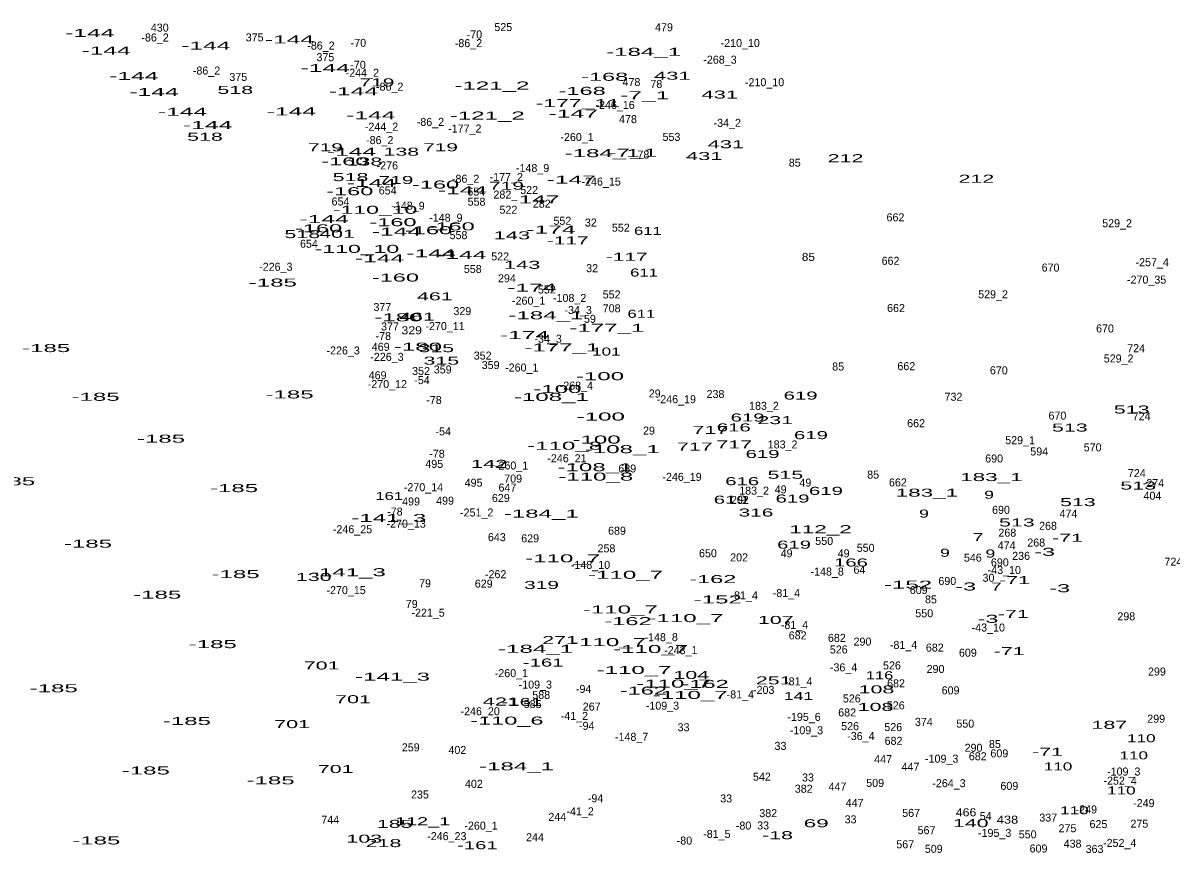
# Model space of a CAD drawing. Extents: x -658595 to -655205, y -1004347 to -1000147.
# Drawn here: x -656989 to -656415, y -1001888 to -1001473 of the extents above; entities that cross this region are included whole.
import ezdxf
from ezdxf.enums import TextEntityAlignment as Align

# ---------------------------------------------------------------- set-up
doc = ezdxf.new("R2010")
doc.units = 0
doc.header["$LTSCALE"] = 1.6
doc.layers.add('24', color=7, linetype='Continuous')

msp = doc.modelspace()

# ---------------------------------------------------------------- texts
at = {"layer": '24'}
for s, width, p in [('-144', 2.3, (-656955.242, -1001479.62)), ('-144', 2.3, (-656897.232, -1001485.9)), ('-144', 2.3, (-656855.392, -1001482.86)), ('-144', 2.3, (-656947.062, -1001488.37)), ('-184_1', 2.25, (-656678.343, -1001489.03)), ('-144', 2.3, (-656837.512, -1001497.13)), ('-144', 2.3, (-656933.172, -1001501.12)), ('719', 1.95, (-656811.637, -1001504.31)), ('-168', 2.2, (-656697.825, -1001501.5)), ('431', 2.05, (-656664.003, -1001500.98)), ('-144', 2.3, (-656923.102, -1001509.11)), ('518', 2, (-656882.477, -1001508.06)), ('-144', 2.3, (-656823.442, -1001508.73)), ('-121_2', 2.25, (-656754.177, -1001505.88)), ('-168', 2.2, (-656709.045, -1001508.54)), ('431', 2.05, (-656640.233, -1001510.4)), ('-177_11', 2.15, (-656711.243, -1001514.69)), ('-7_1', 2.3, (-656677.786, -1001510.76)), ('-144', 2.3, (-656908.832, -1001519)), ('-144', 2.3, (-656854.442, -1001518.81)), ('-144', 2.3, (-656814.692, -1001520.72)), ('-121_2', 2.25, (-656756.487, -1001520.88)), ('-147', 2.3, (-656713.471, -1001519.91)), ('-144', 2.3, (-656896.282, -1001525.66)), ('518', 2, (-656897.637, -1001531.49)), ('719', 1.95, (-656837.387, -1001536.75)), ('-144', 2.3, (-656824.392, -1001538.98)), ('138', 2, (-656799.477, -1001538.95)), ('719', 1.95, (-656779.877, -1001536.75)), ('431', 2.05, (-656637.193, -1001535.23)), ('-160', 2.2, (-656827.701, -1001543.78)), ('138', 2, (-656817.917, -1001543.89)), ('-184_1', 2.25, (-656699.073, -1001539.69)), ('-7_1', 2.3, (-656683.776, -1001539.48)), ('431', 2.05, (-656648.033, -1001541.13)), ('212', 2, (-656577.377, -1001542.2)), ('518', 2, (-656824.867, -1001551.66)), ('-144', 2.3, (-656814.312, -1001554.58)), ('719', 1.95, (-656802.127, -1001553.11)), ('-160', 2.2, (-656782.341, -1001555.39)), ('719', 1.95, (-656746.887, -1001555.98)), ('-147', 2.3, (-656714.511, -1001552.92)), ('212', 2, (-656511.947, -1001552.47)), ('-160', 2.2, (-656825.231, -1001558.72)), ('-144', 2.3, (-656768.852, -1001558.2)), ('-147', 2.3, (-656732.671, -1001562.81)), ('-144', 2.3, (-656838.082, -1001572.66)), ('-110_10', 2.15, (-656812.576, -1001568)), ('-160', 2.2, (-656840.821, -1001577.25)), ('-160', 2.2, (-656803.641, -1001574.2)), ('-144', 2.3, (-656801.942, -1001578.93)), ('-160', 2.2, (-656785.861, -1001578.2)), ('-160', 2.2, (-656774.541, -1001576.29)), ('-174', 2.3, (-656724.641, -1001577.87)), ('611', 1.55, (-656676.209, -1001578.53)), ('518', 2, (-656848.967, -1001580.17)), ('401', 2, (-656831.609, -1001580)), ('143', 2.05, (-656744.203, -1001580.77)), ('-117', 1.95, (-656716.251, -1001583.33)), ('-110_10', 2.15, (-656821.646, -1001587.54)), ('-144', 2.3, (-656784.642, -1001589.78)), ('-144', 2.3, (-656769.232, -1001590.54)), ('-144', 2.3, (-656810.312, -1001592.25)), ('143', 2.05, (-656739.073, -1001595.51)), ('-117', 1.95, (-656686.771, -1001591.49)), ('85', 1.1, (-656595.959, -1001591.56)), ('-160', 2.2, (-656802.411, -1001601.88)), ('611', 1.55, (-656678.129, -1001599.37)), ('-185', 2.25, (-656863.701, -1001604.38)), ('-174', 2.3, (-656734.241, -1001606.94)), ('461', 2, (-656782.708, -1001611.27)), ('-180', 2.25, (-656800.937, -1001621.77)), ('461', 2, (-656791.648, -1001621.45)), ('-184_1', 2.25, (-656727.213, -1001620.74)), ('611', 1.55, (-656679.489, -1001620.02)), ('329', 1.15, (-656794.28, -1001628.25)), ('-174', 2.3, (-656737.851, -1001630.63)), ('-177_1', 2.25, (-656696.707, -1001627.02)), ('-180', 2.25, (-656791.187, -1001636.45)), ('-177_1', 2.25, (-656719.237, -1001636.8)), ('-185', 2.25, (-656977.041, -1001637.14)), ('315', 2, (-656781.987, -1001637.19)), ('101', 1.6, (-656696.97, -1001638.89)), ('315', 2, (-656779.457, -1001643.42)), ('-100', 2.25, (-656700.133, -1001651.19)), ('-100', 2.25, (-656721.443, -1001657.62)), ('-185', 2.25, (-656952.321, -1001661.49)), ('-185', 2.25, (-656855.341, -1001660.31)), ('-108_1', 2.25, (-656724.434, -1001661.55)), ('619', 1.9, (-656599.857, -1001660.88)), ('513', 2, (-656434.337, -1001667.85)), ('-100', 2.25, (-656699.743, -1001671.36)), ('616', 1.9, (-656633.257, -1001676.8)), ('619', 1.9, (-656626.357, -1001671.83)), ('231', 2, (-656612.537, -1001673.16)), ('513', 2, (-656465.257, -1001676.88)), ('-185', 2.25, (-656919.611, -1001682.42)), ('717', 2, (-656644.927, -1001678.02)), ('619', 1.9, (-656594.677, -1001680.66)), ('-110_8', 2.25, (-656717.814, -1001685.95)), ('-100', 2.25, (-656701.863, -1001682.88)), ('-108_1', 2.25, (-656689.014, -1001687.67)), ('717', 2, (-656652.727, -1001686.39)), ('717', 2, (-656633.047, -1001685.34)), ('619', 1.9, (-656618.867, -1001690.08)), ('142', 2.05, (-656755.553, -1001695.03)), ('-108_1', 2.25, (-656702.644, -1001696.69)), ('-185', 2.25, (-656994.541, -1001703.73)), ('-110_8', 2.25, (-656702.254, -1001701.4)), ('616', 1.9, (-656629.037, -1001703.69)), ('515', 2, (-656607.467, -1001700.47)), ('183_1', 2.1, (-656504.475, -1001701.63)), ('-185', 2.25, (-656883.091, -1001707.15)), ('161', 1.55, (-656805.509, -1001711.08)), ('619', 1.9, (-656587.187, -1001708.52)), ('183_1', 2.1, (-656536.705, -1001709.43)), ('9', 1.65, (-656505.636, -1001710.46)), ('513', 2, (-656431.077, -1001705.89)), ('619', 1.9, (-656634.797, -1001712.93)), ('619', 1.9, (-656603.887, -1001712.36)), ('513', 2, (-656461.227, -1001714.15)), ('-141_3', 2.25, (-656805.733, -1001722.09)), ('-184_1', 2.25, (-656729.503, -1001719.89)), ('316', 1.95, (-656622.163, -1001719.35)), ('9', 1.65, (-656538.156, -1001719.88)), ('112_2', 2.1, (-656589.885, -1001727.69)), ('513', 2, (-656491.747, -1001724.33)), ('7', 1.8, (-656511.136, -1001731.67)), ('-71', 2, (-656466.425, -1001732)), ('-185', 2.25, (-656956.121, -1001734.93)), ('619', 1.9, (-656603.117, -1001735.41)), ('9', 1.65, (-656527.696, -1001739.47)), ('9', 1.65, (-656504.966, -1001739.85)), ('-3', 2.2, (-656477.854, -1001739.02)), ('-110_7', 2.25, (-656718.809, -1001742.27)), ('166', 1.9, (-656574.667, -1001744.31)), ('-185', 2.25, (-656882.331, -1001750.14)), ('130', 2, (-656843.254, -1001751.56)), ('-141_3', 2.25, (-656825.903, -1001749.19)), ('-110_7', 2.25, (-656687.369, -1001750.49)), ('319', 1.95, (-656729.373, -1001755.56)), ('-162', 2.2, (-656643.755, -1001752.62)), ('-152', 2.25, (-656546.161, -1001755.4)), ('-3', 2.2, (-656517.324, -1001756.33)), ('7', 1.8, (-656502.006, -1001756.4)), ('-71', 2, (-656492.925, -1001753.12)), ('-3', 2.2, (-656470.344, -1001757.19)), ('-185', 2.25, (-656921.511, -1001760.42)), ('-152', 2.25, (-656641.251, -1001762.82)), ('-110_7', 2.25, (-656689.999, -1001767.82)), ('-162', 2.2, (-656686.165, -1001773.65)), ('-110_7', 2.25, (-656657.179, -1001772.14)), ('107', 2, (-656612.279, -1001773.06)), ('-3', 2.2, (-656506.194, -1001772.5)), ('-71', 2, (-656493.505, -1001770.03)), ('-185', 2.25, (-656893.741, -1001785.15)), ('271', 2, (-656720.103, -1001783.11)), ('-110_7', 2.25, (-656695.869, -1001784.14)), ('-184_1', 2.25, (-656732.353, -1001787.49)), ('-110_7', 2.25, (-656674.839, -1001787.6)), ('-71', 2, (-656495.615, -1001788.66)), ('701', 2, (-656839.309, -1001795.83)), ('-161', 1.9, (-656728.531, -1001794.36)), ('-141_3', 2.25, (-656803.843, -1001801.42)), ('-110_7', 2.25, (-656683.099, -1001798.07)), ('104', 2, (-656654.509, -1001800.59)), ('251', 2, (-656613.297, -1001803.28)), ('116', 1.55, (-656560.409, -1001800.72)), ('-185', 2.25, (-656973.241, -1001807.22)), ('-162', 2.2, (-656678.465, -1001808.37)), ('-110_7', 2.25, (-656663.319, -1001804.89)), ('-162', 2.2, (-656647.555, -1001805.04)), ('108', 2, (-656561.914, -1001807.76)), ('701', 2, (-656823.619, -1001812.67)), ('421', 2.05, (-656749.653, -1001813.84)), ('-161', 1.9, (-656739.181, -1001814.05)), ('-110_7', 2.25, (-656655.069, -1001810.55)), ('141', 1.65, (-656600.879, -1001811.1)), ('108', 2, (-656562.384, -1001816.53)), ('-185', 2.25, (-656906.671, -1001823.58)), ('701', 2, (-656854.049, -1001825.13)), ('-110_6', 2.2, (-656746.699, -1001823.38)), ('187', 2, (-656445.483, -1001825.5)), ('110', 1.6, (-656429.51, -1001832.21)), ('-71', 2, (-656476.415, -1001838.94)), ('110', 1.6, (-656433.31, -1001840.77)), ('-185', 2.25, (-656927.211, -1001848.32)), ('701', 2, (-656832.269, -1001847.58)), ('-184_1', 2.25, (-656741.863, -1001846.23)), ('110', 1.6, (-656471.16, -1001846.29)), ('-185', 2.25, (-656864.831, -1001853.26)), ('110', 1.6, (-656439.5, -1001858.3)), ('466', 1.15, (-656517.13, -1001869.24)), ('110', 1.6, (-656462.98, -1001868.26)), ('185', 2, (-656802.767, -1001875.01)), ('112_1', 1.85, (-656788.801, -1001873.68)), ('69', 2.1, (-656592.041, -1001874.7)), ('140', 2, (-656514.799, -1001874.63)), ('438', 1.2, (-656496.419, -1001872.91)), ('-185', 2.25, (-656951.951, -1001883.29)), ('103', 2, (-656817.984, -1001882.41)), ('-18', 2, (-656611.401, -1001880.67)), ('218', 2, (-656808.377, -1001884.62)), ('-161', 1.9, (-656761.431, -1001885.67))]:
    msp.add_text(s, height=4, dxfattribs=dict(at, width=width)).set_placement(p, align=Align.CENTER)
for s, p in [('-86_2', (-656922.578, -1001481.87)), ('430', (-656920.245, -1001476.93)), ('375', (-656872.803, -1001481.81)), ('-70', (-656762.934, -1001480.32)), ('525', (-656748.497, -1001476.66)), ('479', (-656668.143, -1001476.74)), ('-86_2', (-656839.638, -1001485.9)), ('-70', (-656820.924, -1001484.54)), ('-86_2', (-656765.898, -1001484.69)), ('-210_10', (-656630.037, -1001484.63)), ('375', (-656837.433, -1001491.7)), ('-268_3', (-656640.158, -1001492.96)), ('-86_2', (-656896.858, -1001498.39)), ('-70', (-656821.114, -1001495.49)), ('375', (-656880.983, -1001501.59)), ('-244_2', (-656818.981, -1001499.5)), ('478', (-656684.417, -1001504.14)), ('-210_10', (-656617.867, -1001504.23)), ('-86_2', (-656805.278, -1001506.47)), ('78', (-656671.983, -1001505.08)), ('-246_16', (-656692.6, -1001515.59)), ('-244_2', (-656809.371, -1001526.47)), ('-86_2', (-656784.908, -1001524.06)), ('-177_2', (-656767.737, -1001527.37)), ('478', (-656686.147, -1001522.68)), ('-34_2', (-656636.527, -1001524.53)), ('-86_2', (-656810.258, -1001533.17)), ('-260_1', (-656711.606, -1001531.63)), ('553', (-656664.417, -1001531.55)), ('78', (-656678.453, -1001540.38)), ('85', (-656602.767, -1001544.43)), ('-276', (-656806.455, -1001545.85)), ('-148_9', (-656733.846, -1001547.13)), ('-86_2', (-656767.328, -1001552.49)), ('-177_2', (-656747.007, -1001551.61)), ('-246_15', (-656699.575, -1001553.89)), ('654', (-656806.297, -1001558.33)), ('654', (-656761.987, -1001558.91)), ('282', (-656748.947, -1001560.38)), ('522', (-656735.567, -1001558.11)), ('654', (-656829.877, -1001563.85)), ('-148_9', (-656796.136, -1001565.97)), ('558', (-656761.857, -1001563.93)), ('522', (-656745.937, -1001567.98)), ('282', (-656729.267, -1001564.95)), ('-148_9', (-656777.206, -1001571.96)), ('552', (-656718.947, -1001573.51)), ('662', (-656552.428, -1001571.77)), ('32', (-656704.757, -1001574.38)), ('552', (-656689.747, -1001576.93)), ('529_2', (-656441.63, -1001574.73)), ('654', (-656845.667, -1001584.97)), ('558', (-656770.887, -1001580.68)), ('-226_3', (-656862.218, -1001596.49)), ('522', (-656750.057, -1001591.31)), ('662', (-656554.878, -1001593.5)), ('-257_4', (-656424.072, -1001594.21)), ('558', (-656763.757, -1001597.61)), ('294', (-656746.687, -1001602.25)), ('32', (-656704.087, -1001597.2)), ('670', (-656474.882, -1001596.89)), ('552', (-656726.747, -1001607.85)), ('-270_35', (-656426.851, -1001602.92)), ('-260_1', (-656735.806, -1001613.45)), ('-108_2', (-656715.33, -1001612.09)), ('552', (-656694.317, -1001610.32)), ('529_2', (-656503.65, -1001610.26)), ('377', (-656808.949, -1001616.65)), ('329', (-656768.973, -1001618.65)), ('-34_3', (-656711.067, -1001618.13)), ('708', (-656694.327, -1001617.26)), ('662', (-656552.158, -1001617.13)), ('59', (-656705.173, -1001622.53)), ('-78', (-656808.491, -1001631.09)), ('377', (-656805.139, -1001626.35)), ('-270_11', (-656777.599, -1001626.13)), ('670', (-656447.682, -1001627.33)), ('469', (-656809.783, -1001636.52)), ('-34_3', (-656726.087, -1001632.46)), ('-226_3', (-656828.558, -1001638.34)), ('-226_3', (-656806.638, -1001641.53)), ('352', (-656758.807, -1001640.88)), ('529_2', (-656440.86, -1001642.34)), ('724', (-656432.107, -1001637.19)), ('359', (-656778.783, -1001647.82)), ('359', (-656754.813, -1001645.63)), ('-260_1', (-656739.256, -1001646.87)), ('85', (-656581.087, -1001646.35)), ('662', (-656546.998, -1001646.19)), ('670', (-656500.752, -1001648.26)), ('469', (-656811.323, -1001650.73)), ('352', (-656789.617, -1001648.58)), ('-54', (-656789.139, -1001653.15)), ('-270_12', (-656806.445, -1001655.14)), ('-268_4', (-656711.962, -1001655.91)), ('-78', (-656783.161, -1001663.09)), ('29', (-656672.803, -1001659.85)), ('-246_19', (-656661.98, -1001662.71)), ('238', (-656642.417, -1001660.11)), ('732', (-656523.423, -1001661.48)), ('183_2', (-656618.169, -1001666)), ('670', (-656471.462, -1001670.9)), ('724', (-656429.357, -1001671.21)), ('662', (-656542.118, -1001674.7)), ('-54', (-656778.519, -1001678.81)), ('29', (-656675.653, -1001678.39)), ('183_2', (-656608.849, -1001685.31)), ('529_1', (-656490.114, -1001683.19)), ('570', (-656453.847, -1001686.77)), ('-78', (-656781.641, -1001689.94)), ('-246_21', (-656716.665, -1001692.22)), ('690', (-656503.112, -1001692.33)), ('594', (-656480.557, -1001688.82)), ('495', (-656783.027, -1001695.03)), ('-260_1', (-656744.356, -1001695.85)), ('689', (-656686.518, -1001697.34)), ('724', (-656431.767, -1001699.66)), ('495', (-656763.347, -1001704.44)), ('709', (-656743.562, -1001702.37)), ('-246_19', (-656659.13, -1001701.52)), ('49', (-656597.457, -1001704.37)), ('85', (-656563.587, -1001700.39)), ('662', (-656551.218, -1001704.3)), ('-274', (-656423.465, -1001704.59)), ('-270_14', (-656788.389, -1001706.7)), ('647', (-656746.413, -1001706.87)), ('183_2', (-656623.109, -1001708.43)), ('49', (-656609.817, -1001707.79)), ('404', (-656423.94, -1001710.95)), ('499', (-656794.603, -1001713.82)), ('499', (-656777.603, -1001713.44)), ('629', (-656749.718, -1001712.09)), ('202', (-656630.221, -1001713.07)), ('-78', (-656802.691, -1001718.9)), ('-251_2', (-656761.796, -1001719.34)), ('690', (-656499.682, -1001718.01)), ('474', (-656465.951, -1001719.89)), ('-246_25', (-656823.881, -1001727.72)), ('-270_13', (-656797.055, -1001724.93)), ('689', (-656691.648, -1001728.44)), ('268', (-656476.163, -1001725.99)), ('643', (-656751.717, -1001731.68)), ('629', (-656735.068, -1001732.26)), ('550', (-656588.061, -1001733.57)), ('268', (-656496.513, -1001729.42)), ('268', (-656482.063, -1001734.37)), ('258', (-656696.907, -1001737.27)), ('650', (-656646.177, -1001739.71)), ('49', (-656606.877, -1001739.76)), ('49', (-656578.347, -1001739.76)), ('550', (-656567.331, -1001737)), ('474', (-656496.861, -1001735.83)), ('-148_10', (-656704.907, -1001745.54)), ('202', (-656630.601, -1001741.79)), ('546', (-656513.757, -1001741.91)), ('690', (-656500.252, -1001744.27)), ('236', (-656489.613, -1001741.02)), ('724', (-656413.507, -1001743.93)), ('-262', (-656752.29, -1001750.2)), ('-148_8', (-656586.57, -1001748.86)), ('64', (-656570.457, -1001747.95)), ('-43_10', (-656498.024, -1001748.09)), ('79', (-656787.608, -1001754.74)), ('629', (-656758.278, -1001754.9)), ('690', (-656526.502, -1001753.59)), ('30', (-656505.911, -1001751.98)), ('-270_15', (-656827.075, -1001758.17)), ('-81_4', (-656628.06, -1001760.76)), ('-81_4', (-656606.94, -1001759.6)), ('609', (-656540.812, -1001758.12)), ('85', (-656534.677, -1001762.79)), ('79', (-656794.268, -1001765.06)), ('-221_5', (-656786.096, -1001769.44)), ('550', (-656538.041, -1001769.73)), ('298', (-656437.033, -1001771.23)), ('-81_4', (-656602.91, -1001775.55)), ('-43_10', (-656506.024, -1001776.85)), ('-148_8', (-656669.57, -1001781.68)), ('682', (-656601.323, -1001780.79)), ('682', (-656581.733, -1001782.03)), ('290', (-656568.917, -1001783.89)), ('-81_4', (-656548.38, -1001785.54)), ('-243_1', (-656659.75, -1001788.17)), ('526', (-656580.793, -1001787.83)), ('682', (-656532.763, -1001786.88)), ('609', (-656516.232, -1001789.43)), ('-36_4', (-656578.372, -1001796.77)), ('526', (-656554.193, -1001795.8)), ('-260_1', (-656744.446, -1001799.66)), ('290', (-656532.397, -1001797.58)), ('299', (-656421.718, -1001798.85)), ('-109_3', (-656732.476, -1001805.36)), ('-94', (-656708.315, -1001807.54)), ('-203', (-656618.289, -1001808.03)), ('-81_4', (-656600.79, -1001803.78)), ('682', (-656552.153, -1001804.76)), ('609', (-656524.872, -1001808.26)), ('588', (-656729.517, -1001810.54)), ('-81_4', (-656629.98, -1001810.31)), ('526', (-656574.263, -1001812.32)), ('-246_20', (-656760.055, -1001818.71)), ('585', (-656733.807, -1001815.11)), ('267', (-656704.288, -1001816.38)), ('-109_3', (-656668.916, -1001815.92)), ('682', (-656576.593, -1001819.32)), ('526', (-656552.273, -1001815.78)), ('-41_2', (-656712.94, -1001821.05)), ('-94', (-656706.785, -1001825.98)), ('-195_6', (-656598.147, -1001821.52)), ('526', (-656575.123, -1001826.15)), ('374', (-656538.237, -1001824.02)), ('550', (-656517.511, -1001824.89)), ('299', (-656422.098, -1001822.44)), ('-148_7', (-656684.336, -1001831.49)), ('33', (-656658.367, -1001826.71)), ('-109_3', (-656596.916, -1001828.21)), ('-36_4', (-656569.722, -1001831.11)), ('526', (-656553.523, -1001826.63)), ('259', (-656794.763, -1001836.76)), ('33', (-656609.907, -1001836.03)), ('682', (-656553.393, -1001833.49)), ('290', (-656513.387, -1001836.97)), ('85', (-656502.727, -1001835.08)), ('402', (-656771.455, -1001838.07)), ('447', (-656558.611, -1001842.66)), ('-109_3', (-656529.326, -1001842.42)), ('682', (-656511.303, -1001841.2)), ('609', (-656500.492, -1001839.75)), ('447', (-656544.921, -1001846.46)), ('-109_3', (-656438.316, -1001848.84)), ('542', (-656619.211, -1001851.42)), ('33', (-656596.177, -1001851.82)), ('509', (-656562.577, -1001854.55)), ('-264_3', (-656525.662, -1001854.68)), ('-252_4', (-656440.107, -1001853.42)), ('235', (-656790.157, -1001860.33)), ('402', (-656763.185, -1001855)), ('382', (-656598.297, -1001857.45)), ('447', (-656581.431, -1001856.36)), ('609', (-656495.492, -1001856.02)), ('-94', (-656702.365, -1001862.23)), ('33', (-656637.067, -1001862.29)), ('447', (-656572.871, -1001864.54)), ('-249', (-656428.275, -1001864.63)), ('244', (-656721.516, -1001871.51)), ('-41_2', (-656710.09, -1001868.76)), ('382', (-656616.037, -1001869.66)), ('567', (-656544.598, -1001869.52)), ('54', (-656507.321, -1001871.1)), ('337', (-656476.043, -1001871.87)), ('-249', (-656457.005, -1001867.78)), ('744', (-656835.001, -1001872.97)), ('-260_1', (-656759.616, -1001875.92)), ('-80', (-656628.369, -1001875.87)), ('33', (-656618.617, -1001875.8)), ('33', (-656574.877, -1001872.75)), ('275', (-656466.443, -1001877.2)), ('625', (-656450.943, -1001875.13)), ('275', (-656430.493, -1001874.92)), ('-246_23', (-656776.721, -1001881.16)), ('244', (-656732.646, -1001881.68)), ('-80', (-656657.939, -1001883.36)), ('-81_5', (-656641.736, -1001880.06)), ('567', (-656536.898, -1001878.18)), ('-195_3', (-656502.832, -1001879.51)), ('550', (-656486.321, -1001880.25)), ('567', (-656547.548, -1001885.22)), ('509', (-656533.297, -1001887.49)), ('609', (-656480.902, -1001887.33)), ('438', (-656463.881, -1001884.9)), ('363', (-656452.903, -1001887.54)), ('-252_4', (-656440.307, -1001884.53))]:
    msp.add_text(s, height=4, dxfattribs=at).set_placement(p, align=Align.CENTER)

doc.saveas('drawing.dxf')
